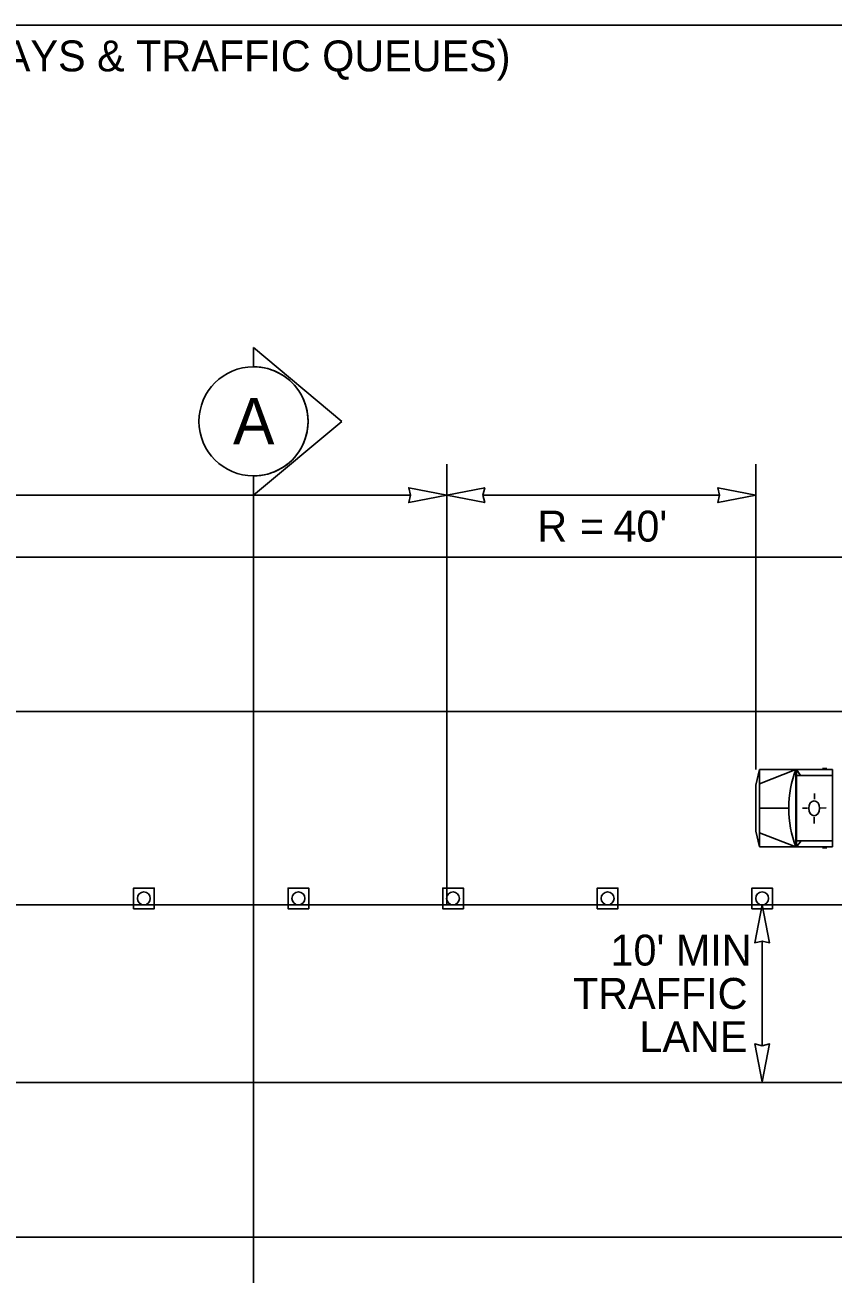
# Model space of a CAD drawing. Extents: x 99999.1 to 100095.7, y 99995 to 100010.7.
# Drawn here: x 100048.842 to 100050.933, y 100005.634 to 100008.869 of the extents above; entities that cross this region are included whole.
import ezdxf

# ---------------------------------------------------------------- set-up
doc = ezdxf.new("R2010")
doc.units = 0
for name, color, linetype in [('RD_ED_ShoulderPavedEdge', 7, 'Continuous'), ('RD_MK_LineEdgeWhite', 7, 'Continuous'), ('RD_MK_LineSkipCenter', 7, 'Continuous'), ('SH_TI_WZSectionCut', 7, 'Continuous'), ('TR_WZ_ProtectiveVehicle', 7, 'Continuous'), ('TR_WZ_TrafficCone', 7, 'Continuous'), ('TR_WZ_WorkZoneDetails', 7, 'Continuous'), ('TR_WZ_WorkZoneTextCurrent', 7, 'Continuous')]:
    doc.layers.add(name, color=color, linetype=linetype)

msp = doc.modelspace()

# ---------------------------------------------------------------- linework, layer by layer
at = {"layer": 'RD_ED_ShoulderPavedEdge'}
for p, q in [((100040.1076, 100007.4923), (100055.6424, 100007.4923)), ((100040.1076, 100005.7323), (100055.6424, 100005.7323))]:
    msp.add_line(p, q, dxfattribs=at)
at = {"layer": 'RD_MK_LineEdgeWhite'}
for p, q in [((100040.1076, 100007.0923), (100055.6424, 100007.0923)), ((100040.1076, 100006.1323), (100055.6424, 100006.1323))]:
    msp.add_line(p, q, dxfattribs=at)
at = {"layer": 'RD_MK_LineSkipCenter'}
msp.add_lwpolyline([(100051.15, 100006.5923), (100043.4767, 100006.5923)], dxfattribs=at)
at = {"layer": 'SH_TI_WZSectionCut'}
for p, q in [((100049.4337, 100007.9847), (100049.4337, 100008.0346)), ((100049.4337, 100008.0346), (100049.6619, 100007.8435)), ((100049.6619, 100007.8435), (100049.4337, 100007.6523)), ((100049.4337, 100007.6523), (100049.4337, 100007.7022)), ((100049.4338, 100007.7022), (100049.4338, 100005.5723))]:
    msp.add_line(p, q, dxfattribs=at)
msp.add_circle((100049.4338, 100007.8435), 0.1412, dxfattribs=at)
msp.add_arc((100049.4338, 100007.8435), 0.1412, 269.9978, 90.0022, dxfattribs=at)
at = {"layer": 'TR_WZ_ProtectiveVehicle'}
for p, q in [((100050.743, 100006.9423), (100050.7338, 100006.902)), ((100050.743, 100006.7423), (100050.743, 100006.9423)), ((100050.743, 100006.9423), (100050.9319, 100006.9423)), ((100050.743, 100006.9057), (100050.8375, 100006.9423)), ((100050.8375, 100006.7423), (100050.8375, 100006.9423)), ((100050.8392, 100006.7423), (100050.8392, 100006.9423)), ((100050.8492, 100006.9268), (100050.8392, 100006.9423)), ((100050.9062, 100006.9451), (100050.9175, 100006.9451)), ((100050.9319, 100006.7423), (100050.9319, 100006.9423)), ((100050.7338, 100006.7827), (100050.7338, 100006.902)), ((100050.8392, 100006.9268), (100050.9319, 100006.9268)), ((100050.8852, 100006.8808), (100050.885, 100006.8658)), ((100050.743, 100006.8423), (100050.8189, 100006.8423)), ((100050.8544, 100006.8422), (100050.867, 100006.8423)), ((100050.8986, 100006.8427), (100050.8986, 100006.8427)), ((100050.9154, 100006.8431), (100050.9005, 100006.8427)), ((100050.8845, 100006.8027), (100050.8845, 100006.8188)), ((100050.743, 100006.7423), (100050.7338, 100006.7827)), ((100050.743, 100006.779), (100050.8375, 100006.7423)), ((100050.743, 100006.7423), (100050.9319, 100006.7423)), ((100050.8392, 100006.7423), (100050.8512, 100006.7578)), ((100050.8392, 100006.7578), (100050.9319, 100006.7578)), ((100050.9062, 100006.7395), (100050.9175, 100006.7395))]:
    msp.add_line(p, q, dxfattribs=at)
msp.add_ellipse((100050.9725, 100006.8424), major_axis=(0, -0.2099), ratio=0.73155, start_param=4.215852, end_param=5.209111, dxfattribs=at)
msp.add_ellipse((100050.8845, 100006.8423), major_axis=(0, 0.0193), ratio=0.73155, dxfattribs=at)
at = {"layer": 'TR_WZ_TrafficCone'}
for points in [[(100049.1234, 100006.6357), (100049.1767, 100006.6357), (100049.1767, 100006.5823), (100049.1234, 100006.5823), (100049.1234, 100006.6357)], [(100049.1234, 100006.5823), (100049.1767, 100006.5823), (100049.1767, 100006.6357), (100049.1234, 100006.6357), (100049.1234, 100006.5823)], [(100049.5234, 100006.6357), (100049.5767, 100006.6357), (100049.5767, 100006.5823), (100049.5234, 100006.5823), (100049.5234, 100006.6357)], [(100049.5234, 100006.5823), (100049.5767, 100006.5823), (100049.5767, 100006.6357), (100049.5234, 100006.6357), (100049.5234, 100006.5823)], [(100049.9234, 100006.6357), (100049.9767, 100006.6357), (100049.9767, 100006.5823), (100049.9234, 100006.5823), (100049.9234, 100006.6357)], [(100049.9234, 100006.5823), (100049.9767, 100006.5823), (100049.9767, 100006.6357), (100049.9234, 100006.6357), (100049.9234, 100006.5823)], [(100050.3234, 100006.6357), (100050.3767, 100006.6357), (100050.3767, 100006.5823), (100050.3234, 100006.5823), (100050.3234, 100006.6357)], [(100050.3234, 100006.5823), (100050.3767, 100006.5823), (100050.3767, 100006.6357), (100050.3234, 100006.6357), (100050.3234, 100006.5823)], [(100050.7234, 100006.6357), (100050.7767, 100006.6357), (100050.7767, 100006.5823), (100050.7234, 100006.5823), (100050.7234, 100006.6357)], [(100050.7234, 100006.5823), (100050.7767, 100006.5823), (100050.7767, 100006.6357), (100050.7234, 100006.6357), (100050.7234, 100006.5823)]]:
    msp.add_lwpolyline(points, dxfattribs=at)
for centre in [(100049.15, 100006.609), (100049.55, 100006.609), (100049.95, 100006.609), (100050.35, 100006.609), (100050.75, 100006.609)]:
    msp.add_circle(centre, 0.0167, dxfattribs=at)
at = {"layer": 'TR_WZ_WorkZoneDetails'}
for p, q in [((100051.3796, 100008.8691), (100044.3704, 100008.8691)), ((100049.9338, 100007.4923), (100049.9338, 100007.7323)), ((100050.7338, 100006.9423), (100050.7338, 100007.7323)), ((100045.2437, 100007.6523), (100049.84, 100007.6523)), ((100050.64, 100007.6523), (100050.0275, 100007.6523)), ((100050.75, 100006.2278), (100050.75, 100006.4986))]:
    msp.add_line(p, q, dxfattribs=at)
for points in [[(100049.9338, 100007.6523), (100049.8355, 100007.6331), (100049.84, 100007.6523), (100049.8355, 100007.6716)], [(100049.9338, 100007.6523), (100050.032, 100007.6331), (100050.0275, 100007.6523), (100050.032, 100007.6716)], [(100050.7338, 100007.6523), (100050.6355, 100007.6331), (100050.64, 100007.6523), (100050.6355, 100007.6716)], [(100045.15, 100007.4923), (100045.15, 100006.5923), (100049.9338, 100006.5923), (100049.9338, 100007.4923)], [(100050.75, 100006.5923), (100050.7308, 100006.4941), (100050.75, 100006.4986), (100050.7693, 100006.4941)], [(100050.75, 100006.1341), (100050.7308, 100006.2324), (100050.75, 100006.2278), (100050.7693, 100006.2324)]]:
    msp.add_lwpolyline(points, close=True, dxfattribs=at)

# ---------------------------------------------------------------- texts
at = {"layer": 'SH_TI_WZSectionCut'}
msp.add_text('A', height=0.12, rotation=359.99, dxfattribs=at).set_placement((100049.3808, 100007.7843))
at = {"layer": 'TR_WZ_WorkZoneTextCurrent'}
for s, p in [('(MINIMIZE DISTANCE BETWEEN MAINLINE FLAGGERS TO MINIMIZE DELAYS & TRAFFIC QUEUES)', (100045.0644, 100008.7491)), ('R', (100050.1681, 100007.5323)), ("40'", (100050.365, 100007.5323)), ('=', (100050.2786, 100007.5323)), ("10' MIN", (100050.3575, 100006.4352)), ('TRAFFIC', (100050.2604, 100006.3232)), ('LANE', (100050.4323, 100006.2112))]:
    msp.add_text(s, height=0.08, dxfattribs=at).set_placement(p)

doc.saveas('drawing.dxf')
